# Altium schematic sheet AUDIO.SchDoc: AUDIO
size A4; Date: Not used; ApprovedBy: Not used; CheckedBy: Not used; Author: Not used; CompanyName: STMicroelectronics; DrawnBy: Not used; Engineer: Not used; Organization: Not used; Address1: Not used; Address2: Not used; Address3: Not used; Address4: Not used; DocumentNumber: Not used; Revision: Not used; SheetNumber: 11; SheetTotal: 16
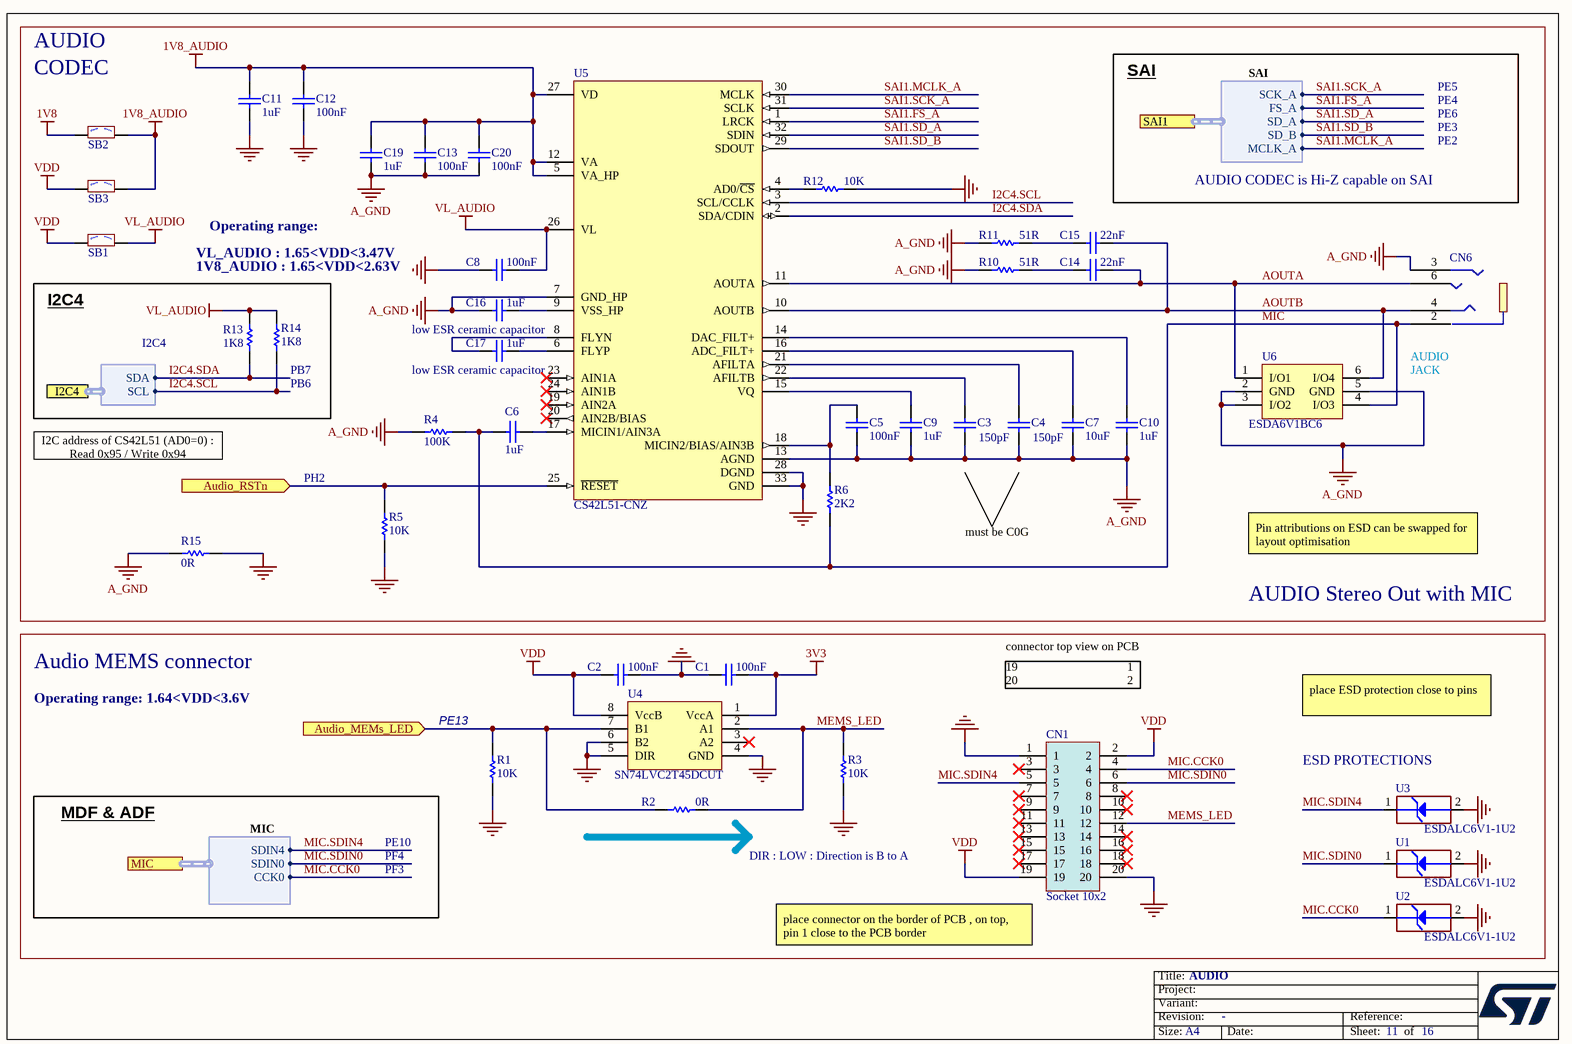
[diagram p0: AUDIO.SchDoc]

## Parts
C1  value 100nF  [C0402]  (hidden comment: Capacitor)
C2  value 100nF  [C0402]  (hidden comment: Capacitor)
C3  value 150pF  [C0603]  (hidden comment: Capacitor)
C4  value 150pF  [C0603]  (hidden comment: Capacitor)
C5  value 100nF  [C0402]  (hidden comment: Capacitor)
C6  value 1uF  [C0402]  (hidden comment: Capacitor)
C7  value 10uF  [C0603]  (hidden comment: Capacitor)
C8  value 100nF  [C0402]  (hidden comment: Capacitor)
C9  value 1uF  [C0402]  (hidden comment: Capacitor)
C10  value 1uF  [C0402]  (hidden comment: Capacitor)
C11  value 1uF  [C0402]  (hidden comment: Capacitor)
C12  value 100nF  [C0402]  (hidden comment: Capacitor)
C13  value 100nF  [C0402]  (hidden comment: Capacitor)
C14  value 22nF  [C0402]  (hidden comment: Capacitor)
C15  value 22nF  [C0402]  (hidden comment: Capacitor)
C16  value 1uF  [C0603]  (hidden comment: Capacitor)
C17  value 1uF  [C0603]  (hidden comment: Capacitor)
C19  value 1uF  [C0402]  (hidden comment: Capacitor)
C20  value 100nF  [C0402]  (hidden comment: Capacitor)
CN1  Socket 10x2  [CON_FCI_20021311-XXX20XXLF]
CN6  Jack_PJ3028B-3_4P  [CON_PHONE-JACK-3P5_HY_PJ3028B]  (value not drawn)
R1  value 10K  [R0402]  (hidden comment: Resistor)
R2  value 0R  [R0402]  (hidden comment: Resistor)
R3  value 10K  [R0402]  (hidden comment: Resistor)
R4  value 100K  [R0402]  (hidden comment: Resistor)
R5  value 10K  [R0402]  (hidden comment: Resistor)
R6  value 2K2  [R0402]  (hidden comment: Resistor)
R10  value 51R  [R0402]  (hidden comment: Resistor)
R11  value 51R  [R0402]  (hidden comment: Resistor)
R12  value 10K  [R0402]  (hidden comment: Resistor)
R13  value 1K8  [R0402]  (hidden comment: Resistor)
R14  value 1K8  [R0402]  (hidden comment: Resistor)
R15  value 0R  [R0402]  (hidden comment: Resistor)
SB1  SB_OFF  [SOLDER-BRIDGE_R0402-0R]  (value not drawn)
SB2  SB_OFF  [SOLDER-BRIDGE_R0402-0R]  (value not drawn)
SB3  SB_OFF  [SOLDER-BRIDGE_R0402-0R]  (value not drawn)
U1  value ESDALC6V1-1U2  [ESD_ST0201]  (hidden comment: ESD-TRANSIL)
U2  value ESDALC6V1-1U2  [ESD_ST0201]  (hidden comment: ESD-TRANSIL)
U3  value ESDALC6V1-1U2  [ESD_ST0201]  (hidden comment: ESD-TRANSIL)
U4  SN74LVC2T45DCUT  [ICC_VSSOP8_DCU_R-PDSO-G8_2X2P30_P050]
U5  CS42L51-CNZ  [ICC_QFN32-EPAD_5X5_P050]
U6  ESDA6V1BC6  [ESD_SOT23-6L]

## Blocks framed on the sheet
I2C4: R13 R14
Audio MEMS connector: C1 C2 CN1 R1-R3 U1-U4

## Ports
Audio_MEMs_LED (in), Audio_RSTn (in), I2C4 (harness I2C4), MIC (harness MIC), SAI1 (harness SAI)

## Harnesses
I2C4: SDA, SCL
MIC: SDIN0, CCK0, SDIN4
SAI: SD_B, FS_A, SD_A, SCK_A, MCLK_A

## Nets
1V8: SB2.1
1V8_AUDIO: C11.2 C12.2 C13.2 C19.2 C20.2 SB2.2 SB3.2 U5.5(VA_HP) U5.12(VA) U5.27(VD)
3V3: C1.2 U4.1(VccA)
A_GND: C3.1 C4.1 C5.1 C7.1 C9.1 C10.1 C13.1 C16.1 C19.1 C20.1 CN6.3 R4.1 R10.1 R11.1 R15.1 U5.7(GND_HP) U5.13(AGND) U6.2(GND) U6.3(I/O2) U6.5(GND)
GND: C1.1 C2.2 C8.2 C11.1 C12.1 CN1.1 CN1.20 R1.1 R3.1 R5.1 R12.2 R15.2 U1.2(GND) U2.2(GND) U3.2(GND) U4.4(GND) U4.5(DIR) U4.6(B2) U5.28(DGND) U5.33(GND)
VDD: C2.1 CN1.2 CN1.19 SB1.1 SB3.1 U4.8(VccB)
VL_AUDIO: C8.1 R13.2 R14.2 SB1.2 U5.26(VL)
AOUTA: C14.2 CN6.6 U5.11(AOUTA) U6.1(I/O1)
AOUTB: C15.2 CN6.4 U5.10(AOUTB) U6.6(I/O4)
Audio_MEMs_LED: R1.2 R2.1 U4.7(B1) ; port Audio_MEMs_LED
Audio_RSTn: R5.2 U5.25(~{RESET}) ; port Audio_RSTn
I2C4.SCL: R14.1 U5.3(SCL/CCLK) ; port I2C4.SCL
I2C4.SDA: R13.1 U5.2(SDA/CDIN) ; port I2C4.SDA
MEMS_LED: CN1.12 R2.2 R3.2 U4.2(A1)
MIC: C6.1 CN6.2 R4.2 R6.1 U6.4(I/O3)
MIC.CCK0: CN1.4 U2.1(IO1) ; port MIC.CCK0
MIC.SDIN0: CN1.6 U1.1(IO1) ; port MIC.SDIN0
MIC.SDIN4: CN1.5 U3.1(IO1) ; port MIC.SDIN4
SAI1.FS_A: U5.1(LRCK) ; port SAI1.FS_A
SAI1.MCLK_A: U5.30(MCLK) ; port SAI1.MCLK_A
SAI1.SCK_A: U5.31(SCLK) ; port SAI1.SCK_A
SAI1.SD_A: U5.32(SDIN) ; port SAI1.SD_A
SAI1.SD_B: U5.29(SDOUT) ; port SAI1.SD_B
NetC3_2: C3.2 U5.22(AFILTB)
NetC4_2: C4.2 U5.21(AFILTA)
NetC5_2: C5.2 R6.2 U5.18(MICIN2/BIAS/AIN3B)
NetC6_2: C6.2 U5.17(MICIN1/AIN3A)
NetC7_2: C7.2 U5.16(ADC_FILT+)
NetC9_2: C9.2 U5.15(VQ)
NetC10_2: C10.2 U5.14(DAC_FILT+)
NetC14_1: C14.1 R10.2
NetC15_1: C15.1 R11.2
NetC16_2: C16.2 U5.9(VSS_HP)
NetC17_1: C17.1 U5.8(FLYN)
NetC17_2: C17.2 U5.6(FLYP)
NetR12_1: R12.1 U5.4(AD0/~{CS})

Not connected (* = marked no-connect by the designer): CN1 3* 7* 8* 9* 10* 11* 13* 14* 15* 16* 17* 18*; U4 3(A2)*; U5 19(AIN2A)* 20(AIN2B/BIAS)* 23(AIN1A)* 24(AIN1B)*

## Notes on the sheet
- AUDIO
- CODEC
- SAI
- PE4
- PE5
- PE6
- AUDIO CODEC is Hi-Z capable on SAI
- PE2
- PE3
- Operating range:
- (near C8) VL_AUDIO : 1.65<VDD<3.47V
- 1V8_AUDIO : 1.65<VDD<2.63V
- PB6
- (near R14) PB7
- low ESR ceramic capacitor
- (near CN6) AUDIO
- JACK
- I2C address of CS42L51 (AD0=0) :
  Read 0x95 / Write 0x94
- PH2
- must be C0G
- Pin attributions on ESD can be swapped for layout optimisation
- connector top view on PCB
- AUDIO Stereo Out with MIC
- Operating range: 1.64<VDD<3.6V
- (near R1) PE13
- 19
- 20
- 1
- 2
- place ESD protection close to pins
- (near U3) ESD PROTECTIONS
- MDF & ADF
- PF4
- PE10
- (near R2) DIR : LOW : Direction is B to A
- PF3
- (near CN1) place connector on the border of PCB , on top, pin 1 close to the PCB border

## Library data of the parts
C1 C2 C5 C8 C12 C13 C20 = MCD-00006: Capacitor, MLCC, 100nF, 16V, X7R, +/-10%, 0402, T=0.5mm; Manufacturer_Part_Number: CC0402KRX7R7BB104; Manufacturer: YAGEO; Part_Preference: Recommended; Order_Code_RS: 616-9701; Component_Country_Of_Origin: China
C3 C4 = MCD-00304: Capacitor, MLCC, 150pF, 50V, COG, +/-5%, 0603, T=0.8mm; Manufacturer_Part_Number: CC0603JRNPO9BN151; Manufacturer: YAGEO; BMS_Part_Number: 9142051; Part_Preference: Recommended; Component_Country_Of_Origin: China
C6 C9-C11 C19 = MCD-01722: Capacitor, MLCC, 1uF, 10V, X5R, +/-10%, 0402, T=0.5mm; Manufacturer_Part_Number: CC0402KRX5R6BB105; Manufacturer: YAGEO; Part_Preference: Recommended; Component_Country_Of_Origin: China
C7 = MCD-00243: Capacitor, MLCC, 10uF, 6V3, X5R, +/-10%, 0603, T=0.8mm; Manufacturer_Part_Number: CC0603KRX5R5BB106; Manufacturer: YAGEO; Part_Preference: Recommended; Component_Country_Of_Origin: China
C14 C15 = MCD-00202: Capacitor, MLCC, 22nF, 16V, X7R, +/-10%, 0402, T=0.5mm; Manufacturer_Part_Number: CC0402KRX7R7BB223; Manufacturer: YAGEO; Part_Preference: Recommended; Component_Country_Of_Origin: China
C16 C17 = MCD-00010: Capacitor, MLCC, 1uF, 16V, X5R, +/-10%, 0603, T=0.8mm; Manufacturer_Part_Number: CC0603KRX5R7BB105; Manufacturer: YAGEO; Part_Preference: Recommended; Component_Country_Of_Origin: China
CN1 = MCD-00147: Socket, 10x2, 1.27mm, VR, TH, T=4.30mm/2.40mm; Part_Type: Connector; Part_Preference: Recommended; Manufacturer: AMPHENOL ICC; Manufacturer_Part_Number: 20021311-00020T4LF; Order_Code_RS: 170-8859; Component_Country_Of_Origin: China
CN6 = MCD-00263: Jack_ Socket-Stereo, 3.5mm, 4 pins, RA, SMD, T=5mm; Part_Type: Connector; Manufacturer: QIAOD; Part_Preference: Recommended; Value: Jack_ Socket-Stereo_PJ3028B-3_4P; Component_Country_Of_Origin: Unknown
R1 R3 R5 R12 = MCD-00053: Resistor, 10K, 0402, +/-1%, 1/16W; Manufacturer_Part_Number: RC0402FR-0710KL; Manufacturer: YAGEO; BMS_Part_Number: 9131590; Part_Preference: Recommended; Component_Country_Of_Origin: China
R2 R15 = MCD-00052: Resistor, 0R, 0402, +/-5%, 1/16W; Manufacturer_Part_Number: RC0402JR-070RL; Manufacturer: YAGEO; Part_Preference: Recommended; Order_Code_RS: 618-5804; Component_Country_Of_Origin: China
R4 = MCD-00059: Resistor, 100K, 0402, +/-1%, 1/16W; Manufacturer_Part_Number: RC0402FR-07100KL; Manufacturer: YAGEO; Part_Preference: Recommended; Component_Country_Of_Origin: China; ShowFields: YES; ID: 2533
R6 = MCD-00057: Resistor, 2K2, 0402, +/-1%, 1/16W; Manufacturer_Part_Number: RC0402FR-072K2L; Manufacturer: YAGEO; Part_Preference: Recommended; Component_Country_Of_Origin: China
R10 R11 = MCD-00485: Resistor, 51R, 0402, +/-1%, 1/16W; Manufacturer_Part_Number: RC0402FR-0751RL; Manufacturer: YAGEO; Part_Preference: Recommended; Component_Country_Of_Origin: China
R13 R14 = MCD-00409: Resistor, 1K8, 0402, +/-1%, 1/16W; Manufacturer_Part_Number: RC0402FR-071K8L; Manufacturer: YAGEO; Part_Preference: Recommended; Component_Country_Of_Origin: China
SB1 SB2 = MCD-02162: Solder Bridge 0402 OFF; Part_Type: Misc; Manufacturer_Part_Number: RC0402JR-070RL; Manufacturer: YAGEO; Part_Preference: Recommended; Order_Code_RS: 618-5804; Component_Country_Of_Origin: China; ShowFields: YES; ID: 4262
SB3 = MCD-02162: Solder Bridge 0402 OFF; Part_Type: Misc; Manufacturer_Part_Number: RC0402JR-070RL; Manufacturer: YAGEO; Part_Preference: Recommended; Order_Code_RS: 618-5804; Component_Country_Of_Origin: China
U1-U3 = MCD-00170: ESD protection 6V1; Part_Type: Diode; Manufacturer: STMICROELECTRONICS; BMS_Part_Number: 9151132; Part_Preference: Recommended; Manufacturer_HQ_COO: EU; Component_Country_Of_Origin: China
U4 = MCD-00264: Dual bit dual supply bus transceiver; Part_Type: IC; Manufacturer: TEXAS INSTRUMENTS; BMS_Part_Number: 9169311; Part_Preference: Recommended; Component_Country_Of_Origin: Thailand
U5 = MCD-00265: Low-Power, Stereo Codec with Headphone Amp; Manufacturer: CIRRUS LOGIC; Part_Type: IC; Part_Preference: Recommended; Component_Country_Of_Origin: China
U6 = MCD-00247: Quad Bidir ESD protection; Manufacturer: STMICROELECTRONICS; Part_Type: Diode; BMS_Part_Number: 9179038; Part_Preference: Recommended; Manufacturer_HQ_COO: EU; Component_Country_Of_Origin: China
